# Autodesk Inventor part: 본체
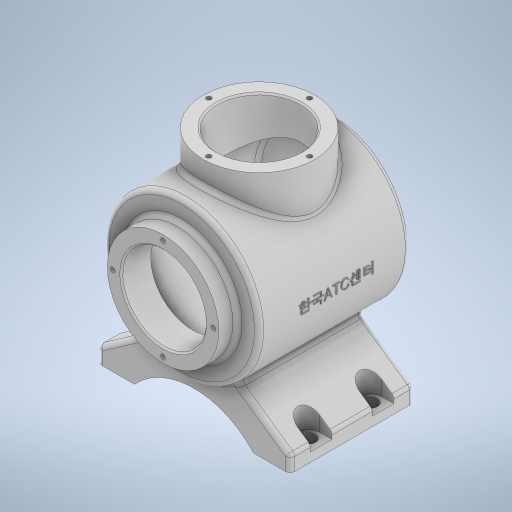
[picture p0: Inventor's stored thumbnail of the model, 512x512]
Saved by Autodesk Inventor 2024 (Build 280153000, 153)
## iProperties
Created: 2023-08
Part Number: 본체
Material: 일반
Document SubType Name: Modeling
Designer: Owner
Density: 1 g/cm^3
Appearance: 기본값
Mass: 478.567 g
Surface Area: 1061.66 cm^2
Volume: 478.567 cm^3
Author: Owner
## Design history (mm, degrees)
sketch "스케치1"
  geometry: L1 (27, 0)-(36, 0); L2 (36, 0)-(36, -12); L3 (36, -12)-(50, -12); L4 (50, -12)-(50, -108.336); L5 (27, 0)-(27, -19); L6 (27, -19)-(43, -19); L7 (43, -19)-(43, -103.887); L8 (0, 0)-(0, -120); A1 r 113 centre (0, -7) between (0, -120) and (50, -108.336); A2 r 106 centre (0, -7) between (0, -113) and (43, -103.887); 1 further point
  constraints: 16 end point, 5 perpendicular, 4 point on circle, 2 centre point, 2 point on line, 2 vertical, 1 concentric, 1 horizontal, 1 horizontal alignment, 1 midpoint
  dimensions: "d12" = 120 distance of L8.start L8.end; "d14" = 54 diameter of L5 L8; "d15" = 72 diameter of L2 L8; "d16" = 100 diameter of L4 L8; "d17" = 86 diameter of L7 L8; "d18" = 19 distance of L1.start L5.end; "d19" = 108 distance from line of L8.end L3; "d90" = 113 radius of A1; "d91" = 7 radial gap between concentric circles of A1 A2
revolve "회전1" sketch "스케치1" stored, may be unused: angle "d22" = 90 deg
node "작업 평면1"
sketch "스케치2"
  geometry: L1 (-26.694, -42.278)-(-62, -67); L2 (-62, -67)-(-62, -77); L3 (-62, -77)-(-38.5, -77); L4 (38.5, -77)-(62, -77); L5 (62, -77)-(62, -67); L6 (62, -67)-(26.694, -42.278); A1 r 50 centre (0, 0) between (-26.694, -42.278) and (26.694, -42.278) reference; A2 r 52.096 centre (0, -112.096) between (38.5, -77) and (-38.5, -77); 6 further points
  constraints: 12 end point, 5 point on circle, 4 midpoint, 3 equal length, 2 perpendicular, 1 centre point, 1 horizontal, 1 horizontal alignment, 1 vertical
  dimensions: "d24" = 10 distance of L4.end L5.end; "d25" = 55 deg angle of L5 L6; "d26" = 77 distance of L4.start L3.end; "d27" = 55 deg angle of L2 L1; "d28" = 17 distance from line of L4 point (0, -60); "d29" = 77 distance from line of L4 point (0, 0); "d30" = 124 distance of point (62, -72) point (-62, -72)
extrude "돌출1" join sketch "스케치2" distance "d31" = 80; taper "d32" = 0 deg
node "작업 평면2"
sketch "스케치4"
  geometry: L1 (-36, 0)-(36, 0) reference; C1 r 36 at (0, -62); 1 further point
  constraints: 1 centre point, 1 vertical alignment
  dimensions: "d34" = 72 diameter of C1; "d35" = 62 distance from line of C1.centre L1
extrude "돌출2" join sketch "스케치4" stored distance "d36" = 80; taper "d37" = 0 deg
sketch "스케치5"
  geometry: C1 r 36 at (0, 0) reference; 2 further points
  constraints: 1 coincident
hole "구멍1" sketch "스케치5" at (0, 0) diameter "d38" = 54; stored, may be unused: countersink angle "d42" = 90 deg, drill point angle "d44" = 0 deg; dims "d39" = 6, "d40" = 4, "d41" = 2, "d43" = 8
sketch "스케치6"
  geometry: C1 r 27 at (0, 0) reference; 2 further points
  constraints: 1 vertical alignment
  dimensions: "d45" = 32.5 distance of point (0, 32.5) C1.centre
hole "구멍2" sketch "스케치6" at (0, 32.5) diameter "d46" = 3.242; stored, may be unused: countersink angle "d50" = 90 deg, drill point angle "d52" = 118 deg; dims "d47" = 8, "d48" = 4, "d49" = 2, "d51" = 10
sketch "스케치8"
  geometry: L1 (23.5, -80)-(0, -80) reference; L2 (23.5, 0)-(23.5, -80) reference; C1 r 4.5 at (15.5, -60); 1 further point
  constraints: 1 centre point
  dimensions: "d56" = 9 diameter of C1; "d57" = 20 distance from line of L1 C1.centre; "d58" = 8 distance from line of L2 C1.centre
extrude "돌출3" cut sketch "스케치8" distance "d59" = 6; taper "d60" = 0 deg
sketch "스케치9"
  geometry: L1 (0, 7)-(8, 7); L2 (8, 60)-(8, -20) reference; L3 (0, -7)-(8, -7); C1 r 4.5 at (0, 0) reference; A1 r 7 centre (0, 0) between (0, 7) and (0, -7); 1 further point
  constraints: 4 end point, 2 point on circle, 2 point on line, 2 tangent, 1 centre point, 1 coincident, 1 horizontal, 1 perpendicular
  dimensions: "d61" = 14 diameter of A1
extrude "돌출4" cut sketch "스케치9" stored distance "d62" = 6; taper "d63" = 0 deg
sketch "스케치10"
  geometry: 2 further points
  constraints: 1 vertical alignment
  dimensions: "d67" = 32.5 distance of point (0, 0) point (0, 32.5)
hole "구멍3" sketch "스케치10" at (0, 32.5) diameter "d68" = 3.242; stored, may be unused: countersink angle "d72" = 90 deg, drill point angle "d74" = 118 deg; dims "d69" = 8, "d70" = 4, "d71" = 2, "d73" = 10
node "작업 평면3"
sketch "스케치11"
  geometry: L1 (-36, 60.168)-(36, 60.168) reference; 3 further points
  constraints: 1 midpoint, 1 vertical alignment, 1 other
  dimensions: "d78" = 62 distance from line of L1 point (0, -1.832)
feature "엠보싱1" sketch "스케치11" dims "d24" = 10, "d25" = 55 deg, "d26" = 77, "d27" = 55 deg, "d28" = 17, "d29" = 77, "d30" = 124, "d79" = 0.5, "d80" = 0
chamfer "모따기1" distance "d81" = 1; stored, may be unused: second distance "d82" = 2, angle "d83" = 45 deg
fillet "모깎기1" dims "d84" = 3
fillet "모깎기2" dims "d85" = 3
fillet "모깎기3" dims "d86" = 3
fillet "모깎기5" dims "d88" = 3
node "솔리드1"
pattern_circular "원형 패턴1" dims angle "d54" = 360 deg
pattern_linear "직사각형 패턴1" dims "d66" = 40
mirror "미러1"
pattern_circular "원형 패턴2" dims angle "d76" = 360 deg
feature "A9D066F2-1C7D-4E18-AEED-F7BC21143FA4" dims "d38" = 54, "d39" = 6, "d40" = 4, "d41" = 2, "d42" = 90 deg, "d43" = 8, "d44" = 0
other parameters: "d33" = 65
